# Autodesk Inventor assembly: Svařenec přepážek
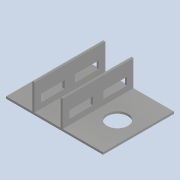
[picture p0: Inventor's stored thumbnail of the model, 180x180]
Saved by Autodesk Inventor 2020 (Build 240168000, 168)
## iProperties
Created: 2025-03
Part Number: Svařenec přepážek
Document SubType Name: Assembly
Designer: doma
Author: doma
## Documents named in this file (3)
- C:\Users\doma\Desktop\škola\DP\Inventor\Svařenec přepážek.iam
- C:\Users\doma\Desktop\škola\DP\Inventor\Víko bedýnky.ipt
- C:\Users\doma\Desktop\škola\DP\Inventor\Přepážka bedýnky.ipt
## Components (3 placed, 2 different names)
1. Víko bedýnky:1 — Stejný směr:1, Stejný směr:2, Proti sobě:1, Proti sobě:2, Stejný směr:3
2. Přepážka bedýnky:1 — Stejný směr:1, Proti sobě:2, Proti sobě:3
3. Přepážka bedýnky:2 — Stejný směr:2, Proti sobě:1, Proti sobě:3, Stejný směr:3
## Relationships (6: Flush 3, Mate 3)
- Stejný směr:1 [Flush]: Víko bedýnky:1 ↔ Přepážka bedýnky:1
- Stejný směr:2 [Flush]: Víko bedýnky:1 ↔ Přepážka bedýnky:2
- Proti sobě:1 [Mate]: Víko bedýnky:1 ↔ Přepážka bedýnky:2
- Proti sobě:2 [Mate]: Víko bedýnky:1 ↔ Přepážka bedýnky:1
- Proti sobě:3 [Mate]: Přepážka bedýnky:1 ↔ Přepážka bedýnky:2
- Stejný směr:3 [Flush]: Víko bedýnky:1 ↔ Přepážka bedýnky:2
